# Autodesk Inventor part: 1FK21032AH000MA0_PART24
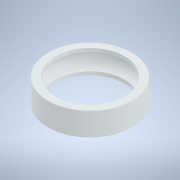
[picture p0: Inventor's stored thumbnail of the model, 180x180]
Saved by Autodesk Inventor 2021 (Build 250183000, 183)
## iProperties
Created: 2025-04
Part Number: 1FK21032AH000MA0_PART24
Material: Generic
Catalog Web Link: www.3dfindit.com
Description: -Servo synchronous motor
Document SubType Name: Modeling
Designer: psAdmin
Mass: 1.46378 g
Surface Area: 23.3636 cm^2
Volume: 1.46378 cm^3
Density: 1 g/cm^3
Appearance: PSOLRGB-212-217-219
Category: PARTsolutions
Title: 1FK21032AH000MA0_PART24
Author: Cadenas PARTsolutions
Comments: Servo synchronous motor
Sending System: PARTsolutions
Preprocessor: ST-DEVELOPER v19.3
PSOL_IDENT_0: {$CADENAS_DATA/23d-libs/siemens_ag/_cat_/45/10/1fk21032ah000ma0.prj},216 {VTYP=3D},{NB=1FK21032AH000
PSOL_IDENT_1: MA0_PART24},{LINA=1FK21032AH000MA0_PART24},{NN=1FK21032AH000MA0_PART24},{NOPRJ=TRUE},{DATE=19.08.202
PSOL_IDENT_2: 5 14:00:35},{GEOMDATE=30.07.2025 02:02:03},{VERSION=},{LINEID=10},{WBVAR=},{WBNUMERIC=}  {NB=1FK2103
PSOL_IDENT_3: 2AH000MA0_PART24},{LINA=1FK21032AH000MA0_PART24},{KT=DUMMY},{PREVIEW=../../../_pool_/14/8e/p_d211_xx
PSOL_IDENT_4: _00426j.png},{DESCSHORT=SIMOTICS S-1FK2 HD, SINAMICS S210 3AC 400V-480V, 0.59 Nm, 4500 rpm},{DESCLON
PSOL_IDENT_5: G=SIMOTICS S-1FK2 HD servo motor M0=0.64 Nm; PN = 0.28 kW at nN=4500 rpm (380-480 V); PN = 0.167 kW
PSOL_IDENT_6: at nN=2500 rpm (200-240 V); degree of protection IP64; cylindrical shaft D14 x 30 mm; absolute encod
PSOL_IDENT_7: er 22-bit + 12-bit multiturn (encoder AM22DQC); with OCC interface; plug size M17, rotatable; SIMOTI
PSOL_IDENT_8: CS S-1FK2 servomotorfor a wide range of uses in industrial environments. SIMOTICS S‑1FK2 servomotors
PSOL_IDENT_9: are compact synchronous motors with a high dynamic performance that set themselves apart as a resul
PSOL_IDENT_10: t of their high power density, degree of protection and overload capability. The motors are availabl
PSOL_IDENT_11: e in two variants: as High Dynamic variant (highest dynamic performance as a result of the low intri
PSOL_IDENT_12: nsic moment of inertia for applications demanding a high dynamic performance with low moved masses)
PSOL_IDENT_13: - and as Compact variant (precise and stable closed-loop control for medium up to large moved masses
PSOL_IDENT_14: as a result of a medium intrinsic moment of inertia). SIMOTICSS‑1FK2 servomotors fully exploit thei
PSOL_IDENT_15: r strengths in a system with the SINAMICSS210 frequency converter and simple connection using the on
PSOL_IDENT_16: e cable connection (OCC). Advantages include the short control and positioning times, fast and preci
PSOL_IDENT_17: se correction of disturbing quantities as well as stable control with a high dynamic performance. Th
PSOL_IDENT_18: e servo motors can be configured to address a wide range of requirements. For example with and witho
PSOL_IDENT_19: ut holding brake, IP64 or IP65 degree of protection, singleturn or multiturn absolute encoders - to
PSOL_IDENT_20: name just a few. Further, the servomotors are available in different shaft heights extending from 20
PSOL_IDENT_21: to 100. A shaft sealing ring is available to achieve an IP65 degree of protection and for subsequen
PSOL_IDENT_22: t mounting at the motor or as spare part. SIMOTICS - the optimum motor for each and every motion con
PSOL_IDENT_23: trol application.},{INTNO=195125335004},{SUPPLIERALTNO=1FK2103-2AH00-0MA0},{MANUID=1FK21032AH000MA0}
PSOL_IDENT_24: ,{MANUNAME=Siemens},{MANUTYPEDESC=SYNCHRONOUS MOTOR 1FK2 HD 0,64 NM},{AAU732=SIMOTICS},{AAO057=S-1FK
PSOL_IDENT_25: 2},{AAU734=SIMOTICS S-1FK2 HD servo motor M0=0.64 Nm; PN = 0.28 kW at nN=4500 rpm (380-480 V); PN =
PSOL_IDENT_26: 0.167 kW at nN=2500 rpm (200-240 V); degree of protection IP64; cylindrical shaft D14 x 30 mm; absol
PSOL_IDENT_27: ute encoder 22-bit + 12-bit multiturn (encoder AM22DQC); with OCC interface; plug size M17, rotatabl
PSOL_IDENT_28: e;},{AAW338=SYNCHRONOUS MOTOR 1FK2 HD 0,64 NM},{AAO742=SIMOTICS},{AAO663=4034106444624},{NOCUPEROU=1
PSOL_IDENT_29: },{PRICEQUANTITY=1},{QUANTITYMIN=1},{QUANTITYINT=1},{CTN=85015100},{COO=RO},{AAO676=1FK2103-2AH00-0M
PSOL_IDENT_30: A0},{AAO677=Siemens AG},{ORDERUNIT=C62},{CONTENTUNIT=C62}
NB: 1FK21032AH000MA0_PART24
NT: Servo synchronous motor
NBSYN: $MANUID._PART24
LINA: 1FK21032AH000MA0_PART24
CATALOG: SIEMENS
PREVIEW: ../../../_pool_/14/8e/p_d211_xx_00426j.png
DESCSHORT: SIMOTICS S-1FK2 HD, SINAMICS S210 3AC 400V-480V, 0.59 Nm, 4500 rpm
DESCLONG: SIMOTICS S-1FK2 HD servo motor M0=0.64 Nm; PN = 0.28 kW at nN=4500 rpm (380-480 V); PN = 0.167 kW at nN=2500 rpm (200-240 V); degree of protection IP64; cylindr
INTNO: 195125335004
SUPPLIERALTNO: 1FK2103-2AH00-0MA0
MANUID: 1FK21032AH000MA0
MANUNAME: Siemens
MANUTYPEDESC: SYNCHRONOUS MOTOR 1FK2 HD 0,64 NM
AAU732: SIMOTICS
AAO057: S-1FK2
AAU734: SIMOTICS S-1FK2 HD servo motor M0=0.64 Nm; PN = 0.28 kW at nN=4500 rpm (380-480 V); PN = 0.167 kW at nN=2500 rpm (200-240 V); degree of protection IP64; cylindr
AAW338: SYNCHRONOUS MOTOR 1FK2 HD 0,64 NM
AAO742: SIMOTICS
AAO663: 4034106444624.0
NOCUPEROU: 1
PRICEQUANTITY: 1
QUANTITYMIN: 1
QUANTITYINT: 1
CTN: 85015100
COO: RO
ARTICLENO: 1FK21032AH000MA0_PART24
BOMINFO: 1FK21032AH000MA0_PART24
CREATOR: CADENAS GmbH
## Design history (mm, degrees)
feature "2025_04_17_15_00_20_0760"
body "Solid1"
